// Mitsubishi GX Works2 project: JK3U从站   PLC: FX3U/FX3UC

PROGRAM MAIN
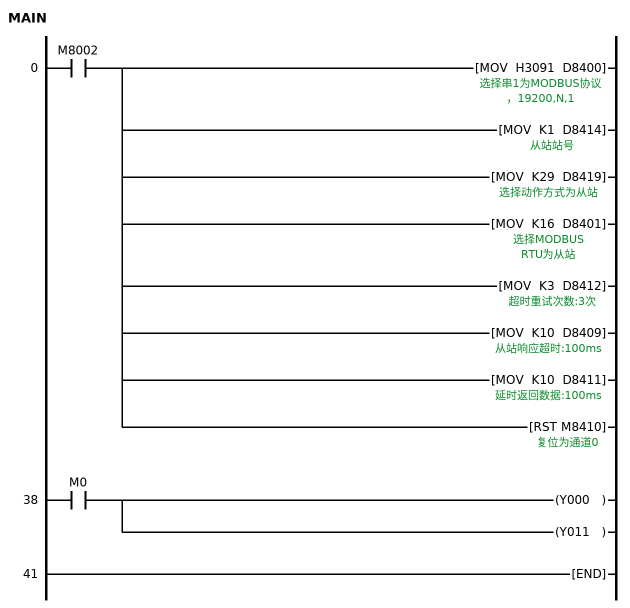
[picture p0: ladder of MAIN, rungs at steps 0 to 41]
0     LD      M8002
      MOV     H3091 D8400  ; 选择串1为MODBUS协议，19200,N,1
      MOV     K1 D8414  ; 从站站号
      MOV     K29 D8419  ; 选择动作方式为从站
      MOV     K16 D8401  ; 选择MODBUS RTU为从站
      MOV     K3 D8412  ; 超时重试次数:3次
      MOV     K10 D8409  ; 从站响应超时:100ms
      MOV     K10 D8411  ; 延时返回数据:100ms
      RST     M8410  ; 复位为通道0
38    LD      M0
      OUT     Y000
      OUT     Y011
41    END
END_PROGRAM

// device comments not shown above
D0  ; 站  功码  地址   数据数 主站内容
